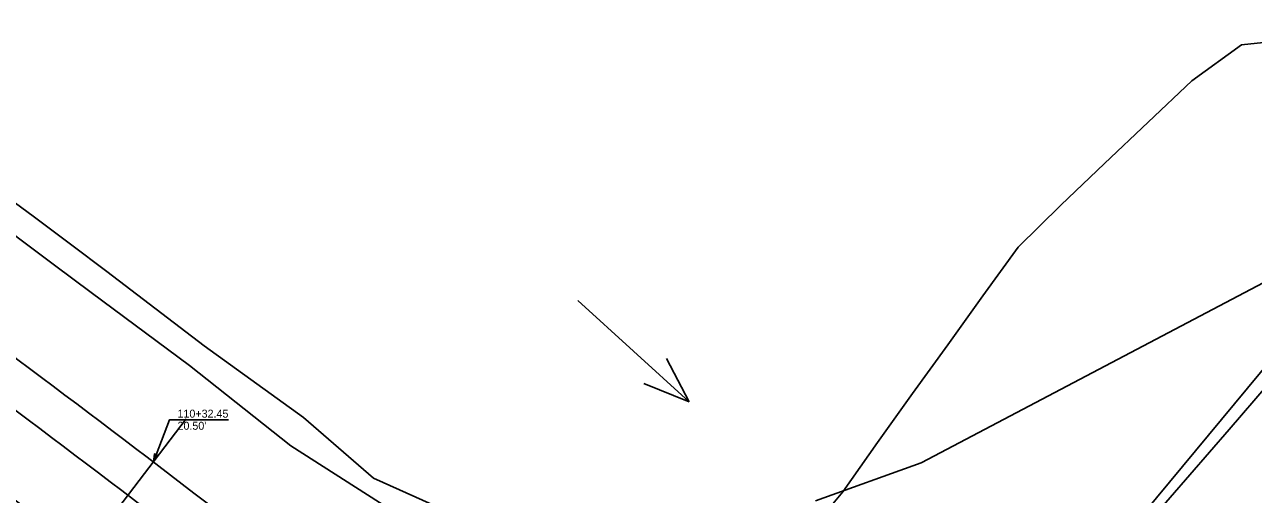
# Model space of a CAD drawing. Extents: x 1006695 to 1009377, y 1883329 to 1886115.
# Drawn here: x 1007771.4 to 1007873.9, y 1884834.1 to 1884873.3 of the extents above; entities that cross this region are included whole.
import ezdxf

# ---------------------------------------------------------------- set-up
doc = ezdxf.new("R2010")
doc.units = 0
for name, color, linetype in [('B_Hatch', 7, 'Continuous'), ('R_I-30 Information', 7, 'Continuous'), ('R_No Plot', 7, 'Continuous'), ('R_Prop Const Limits Cut', 7, 'Continuous'), ('R_Prop EOL', 7, 'Continuous'), ('R_Prop EOS', 7, 'Continuous'), ('R_Prop Guardrail', 7, 'Continuous'), ('R_Water Annot', 7, 'Continuous')]:
    doc.layers.add(name, color=color, linetype=linetype)

msp = doc.modelspace()

# ---------------------------------------------------------------- linework, layer by layer
at = {"layer": 'B_Hatch'}
msp.add_line((1007793.56, 1884838.12), (1007802.65, 1884832.32), dxfattribs=at)
msp.add_line((1007793.56, 1884838.12), (1007802.65, 1884832.32), dxfattribs=at)
for points in [[(1007800.46, 1884835.43), (1007794.61, 1884840.48), (1007786.34, 1884846.48), (1007778.22, 1884852.68), (1007775.19, 1884854.97), (1007772.08, 1884857.31), (1007770.08, 1884858.76), (1007762.04, 1884864.71), (1007753.8, 1884870.38), (1007752.83, 1884871.14)], [(1007752.83, 1884871.14), (1007761.53, 1884863.02), (1007768.81, 1884857.07), (1007770.75, 1884855.55), (1007773.86, 1884853.21), (1007776.9, 1884850.93), (1007785.1, 1884844.84), (1007793.56, 1884838.12)], [(1007752.83, 1884871.14), (1007761.53, 1884863.02), (1007768.81, 1884857.07), (1007770.75, 1884855.55), (1007773.86, 1884853.21), (1007776.9, 1884850.93), (1007785.1, 1884844.84), (1007793.56, 1884838.12)], [(1007863.62, 1884831.18), (1007885.3, 1884857.33), (1007846.15, 1884836.71), (1007837.33, 1884833.53)], [(1007806.73, 1884832.62), (1007800.46, 1884835.43)]]:
    msp.add_lwpolyline(points, dxfattribs=at)
at = {"layer": 'R_I-30 Information'}
for points in [[(1007836.41, 1884830.46), (1007839.61, 1884834.3), (1007842.51, 1884838.4), (1007845.43, 1884842.49), (1007848.36, 1884846.57), (1007851.3, 1884850.64), (1007854.23, 1884854.71), (1007857.81, 1884858.22), (1007861.44, 1884861.69), (1007865.09, 1884865.14), (1007868.73, 1884868.58), (1007872.88, 1884871.6), (1007879.7, 1884872.32)], [(1007875.1, 1884843.27), (1007871.83, 1884839.49), (1007868.56, 1884835.71), (1007865.28, 1884831.93), (1007862.01, 1884828.15), (1007858.74, 1884824.37), (1007855.46, 1884820.59), (1007852.19, 1884816.81), (1007848.92, 1884813.03), (1007845.64, 1884809.25), (1007842.37, 1884805.47), (1007839.09, 1884801.69), (1007835.82, 1884797.91), (1007832.55, 1884794.13), (1007829.27, 1884790.35), (1007826, 1884786.57), (1007822.73, 1884782.8), (1007819.45, 1884779.02), (1007816.18, 1884775.24), (1007813.22, 1884771.82), (1007809.95, 1884768.04), (1007806.67, 1884764.26), (1007803.14, 1884760.19), (1007799.87, 1884756.41)]]:
    msp.add_lwpolyline(points, dxfattribs=at)
at = {"layer": 'R_No Plot'}
for p, q in [((1007784.83, 1884840.37), (1007769.67, 1884820.49)), ((1007784.11, 1884840.31), (1007788.36, 1884840.31))]:
    msp.add_line(p, q, dxfattribs=at)
msp.add_lwpolyline([(1007782.1, 1884836.79), (1007783.45, 1884840.31), (1007784.11, 1884840.31)], dxfattribs=at)
msp.add_lwpolyline([(1007782.1, 1884836.79), (1007782.18, 1884837.45), (1007782.48, 1884837.33)], close=True, dxfattribs=at)
at = {"layer": 'R_Prop Const Limits Cut'}
for points in [[(1007745.92, 1884876.54), (1007753.8, 1884870.38), (1007762.04, 1884864.71), (1007770.08, 1884858.76), (1007772.08, 1884857.31), (1007775.19, 1884854.97), (1007778.22, 1884852.68), (1007786.34, 1884846.48), (1007794.61, 1884840.48), (1007800.46, 1884835.43)], [(1007837.33, 1884833.53), (1007846.15, 1884836.71), (1007885.3, 1884857.33), (1007863.62, 1884831.18)], [(1007800.46, 1884835.43), (1007806.73, 1884832.62)]]:
    msp.add_lwpolyline(points, dxfattribs=at)
at = {"layer": 'R_Prop EOL'}
msp.add_arc((1006901.08, 1883681.49), 1443.39, 37.04506, 53.47197, dxfattribs=at)
at = {"layer": 'R_Prop EOS'}
msp.add_arc((1006901.08, 1883681.49), 1452.89, 51.92135, 53.47197, dxfattribs=at)
at = {"layer": 'R_Prop Guardrail'}
msp.add_arc((1006901.08, 1883681.49), 1449.39, 51.92135, 53.47197, dxfattribs=at)
at = {"layer": 'R_Water Annot'}
for p, q in [((1007817.5, 1884850.25), (1007826.79, 1884841.79)), ((1007826.79, 1884841.79), (1007824.89, 1884845.41)), ((1007826.79, 1884841.79), (1007823, 1884843.34))]:
    msp.add_line(p, q, dxfattribs=at)

# ---------------------------------------------------------------- texts
at = {"layer": 'R_No Plot'}
for s, p in [('110+32.45', (1007784.11, 1884840.48)), ("20.50'", (1007784.11, 1884839.47))]:
    msp.add_text(s, height=0.668, dxfattribs=at).set_placement(p)

doc.saveas('drawing.dxf')
